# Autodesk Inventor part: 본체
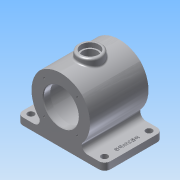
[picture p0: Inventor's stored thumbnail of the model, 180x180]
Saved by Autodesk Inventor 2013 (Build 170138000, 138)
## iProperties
Company: 한국ATC센터
Created: 2014-08
Part Number: 본체
Document SubType Name: Modeling
Designer: KYOUNG IL JANG
Density: 2.71 g/cm^3
Material: 알루미늄-6061
Mass: 1595.16 g
Surface Area: 933.382 cm^2
Volume: 588.618 cm^3
Author: KYOUNG IL JANG
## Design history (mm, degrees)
sketch "스케치1"
  geometry: L1 (-50, 0)-(50, 0); L2 (-36.062, 36.062)-(36.062, 36.062); L3 (36.062, 36.062)-(36.062, -36.062); L4 (36.062, -36.062)-(-36.062, -36.062); L5 (-36.062, -36.062)-(-36.062, 36.062); A1 r 53.623 centre (-3.623, 0) between (36.062, -36.062) and (36.062, 36.062); A2 r 53.623 centre (3.623, 0) between (-36.062, 36.062) and (-36.062, -36.062); A3 r 53.623 centre (0, -3.623) between (36.062, 36.062) and (-36.062, 36.062); A4 r 53.623 centre (0, 3.623) between (-36.062, -36.062) and (36.062, -36.062); 4 further points
  constraints: 11 point on circle, 10 end point, 5 coincident, 4 centre point, 4 horizontal alignment, 3 equal radius, 2 horizontal, 2 parallel, 2 perpendicular, 1 midpoint
  dimensions: "d83" = 51 distance of L2.end point (0, 0); "d84" = 100 distance of L1.end L1.start
extrude "돌출1" new body sketch "스케치1" stored distance "d9" = 100; taper "d10" = 0 deg
node "작업 평면1"
sketch "스케치2"
  geometry: L1 (75, 50)-(-75, 50); L2 (-75, 50)-(-75, -50); L3 (-75, -50)-(75, -50); L4 (75, -50)-(75, 50); 4 further points
  constraints: 8 end point, 3 midpoint, 2 parallel, 2 vertical alignment, 1 horizontal, 1 horizontal alignment, 1 perpendicular
  dimensions: "d14" = 150 distance of L2.end L3.end; "d82" = 100 distance of L1.end L2.end
extrude "돌출2" join sketch "스케치2" distance "d15" = 12; taper "d16" = 0 deg
node "작업 평면3"
  node "작업 평면4"
sketch "스케치3"
  geometry: C1 r 20 at (0, 0); 1 further point
  constraints: 2 coincident, 1 centre point
  dimensions: "d19" = 40 diameter of C1
extrude "돌출3" join sketch "스케치3" stored distance "d23" = 12; taper "d24" = 0 deg
node "작업 평면6"
  node "작업 평면5"
sketch "스케치4"
  geometry: C1 r 37.5 at (0, 0); 1 further point
  constraints: 1 centre point, 1 coincident
  dimensions: "d25" = 75 diameter of C1
extrude "돌출4" cut sketch "스케치4" stored distance "d26" = 76; taper "d27" = 0 deg
sketch "스케치5"
  geometry: C1 r 30 at (0, 0); 1 further point
  constraints: 1 centre point, 1 coincident
  dimensions: "d28" = 60 diameter of C1
extrude "돌출5" cut sketch "스케치5" stored distance "d29" = 116; taper "d30" = 0 deg
hole "구멍1" diameter "d33" = 25; stored, may be unused: countersink angle "d37" = 90 deg, drill point angle "d39" = 0 deg; dims "d31" = 10, "d32" = 10, "d34" = 6, "d35" = 30, "d36" = 8, "d38" = 40
sketch "스케치6"
  geometry: L1 (-75, -50)-(-75, 50) reference; L2 (-75, 50)-(75, 50) reference; L3 (75, -50)-(-75, -50) reference; L4 (75, 50)-(75, -50) reference; L5 (0, -50)-(0, 50); L6 (-75, 0)-(75, 0); L7 (-63, -38)-(63, 38); C1 r 5.5 at (-63, -38); C2 r 5.5 at (-63, 38); C3 r 5.5 at (63, -38); C4 r 5.5 at (63, 38); 2 further points
  constraints: 6 end point, 6 midpoint, 4 centre point, 2 equal radius, 2 horizontal alignment, 2 vertical alignment
  dimensions: "d49" = 11 diameter of C1; "d50" = 11 diameter of C2; "d100" = 12 distance from line of L2 C2.centre; "d101" = 12 distance from line of C2.centre L1
extrude "돌출6" cut sketch "스케치6" distance "d53" = 116; taper "d54" = 0 deg
sketch "스케치8"
  geometry: L1 (75, 50)-(75, -50) reference; 2 further points
  constraints: 1 horizontal alignment, 1 other
  dimensions: "d55" = 12 distance from line of L1 point (63, 0)
feature "엠보싱1" sketch "스케치8" dims "d57" = 1, "d58" = 0, "d83" = 51, "d84" = 100
fillet "모깎기2" dims "d60" = 10
fillet "모깎기5" dims "d63" = 10
fillet "모깎기7" dims "d65" = 3
sketch "스케치9"
  geometry: L1 (0, 0)-(-28.284, 28.284); L2 (0, 0)-(0, 40); C1 r 30 at (0, 0) reference; A1 r 40 centre (0, 0) between (-28.284, 28.284) and (0, 40); 1 further point
  constraints: 4 end point, 2 coincident, 2 point on circle, 1 centre point, 1 vertical
  dimensions: "d66" = 80 diameter of A1; "d67" = 45 deg angle of L1 L2
hole "M4" sketch "스케치9" at (-28.284, 28.284) diameter "d68" = 3.242; stored, may be unused: countersink angle "d72" = 90 deg, drill point angle "d74" = 118 deg; dims "d69" = 8, "d70" = 30, "d71" = 8, "d73" = 10
fillet "모깎기8" dims "d78" = 3
chamfer "모따기1" distance "d79" = 1; stored, may be unused: second distance "d80" = 2, angle "d81" = 45 deg
node "솔리드1"
pattern_circular "원형 패턴1" dims angle "d76" = 360 deg
mirror "대칭1"
